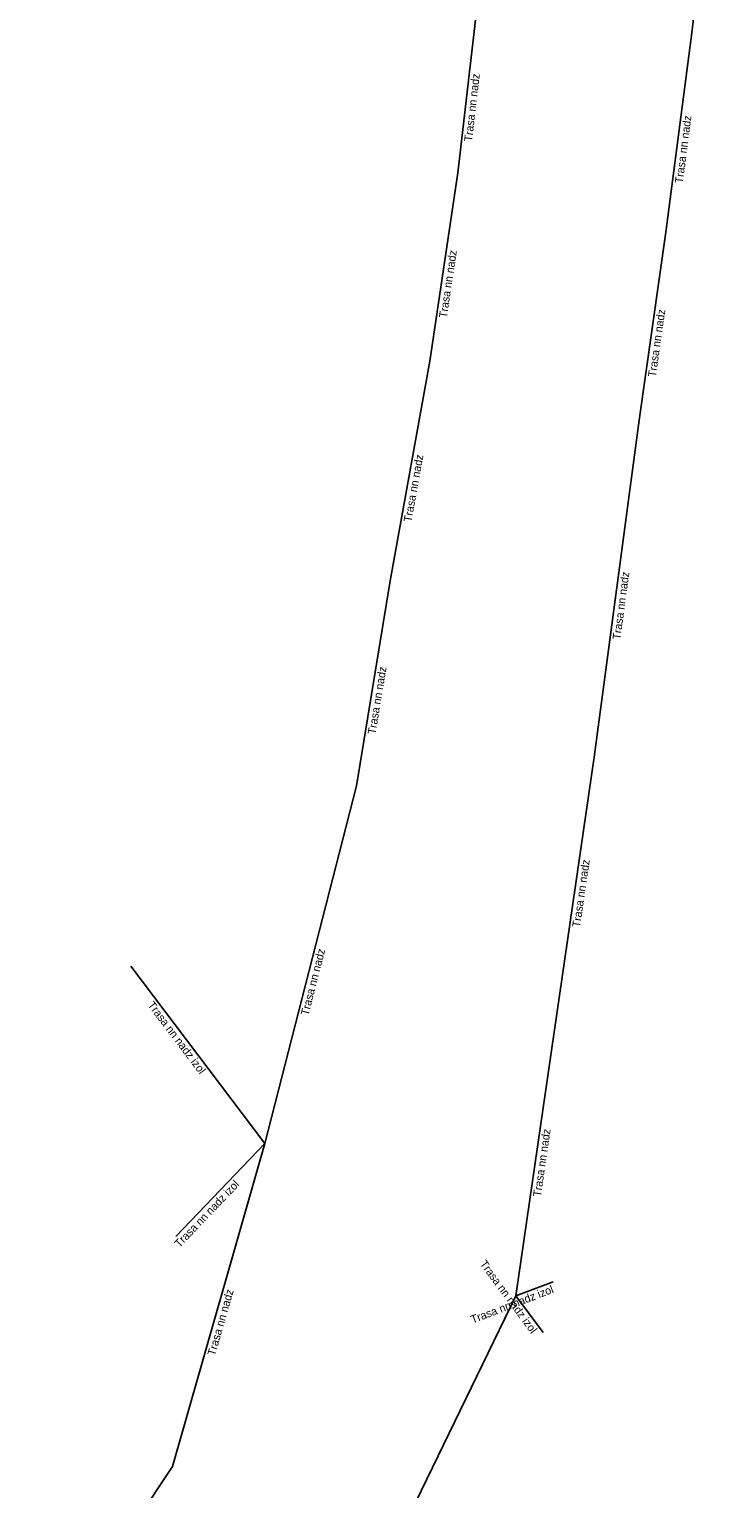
# Model space of a CAD drawing. Extents: x -772942 to -772530, y -1033745 to -1033298.
# Drawn here: x -772845.2 to -772802.4, y -1033493.3 to -1033402.1 of the extents above; entities that cross this region are included whole.
import ezdxf

# ---------------------------------------------------------------- set-up
doc = ezdxf.new("R2010")
doc.units = 0
doc.layers.add('Popiskový text - Ostatní atributy Trasy', color=7, linetype='Continuous')
doc.layers.add('Spojnice NN', color=7, linetype='Continuous')

msp = doc.modelspace()

# ---------------------------------------------------------------- linework, layer by layer
at = {"layer": 'Spojnice NN'}
for points in [[(-772803.783, -1033402.328), (-772802.408, -1033390.528)], [(-772818.393, -1033411.073), (-772817.209, -1033400.814)], [(-772805.397, -1033414.774), (-772803.783, -1033402.328)], [(-772820.15, -1033422.849), (-772818.393, -1033411.073)], [(-772807.07, -1033426.538), (-772805.397, -1033414.774)], [(-772822.626, -1033436.582), (-772820.15, -1033422.849)], [(-772809.879, -1033447.599), (-772807.07, -1033426.538)], [(-772824.733, -1033449.385), (-772822.626, -1033436.582)], [(-772812.043, -1033462.494), (-772809.879, -1033447.599)], [(-772830.454, -1033471.742), (-772824.733, -1033449.385)], [(-772838.843, -1033460.652), (-772830.454, -1033471.742)], [(-772814.771, -1033481.263), (-772812.043, -1033462.494)], [(-772836.223, -1033491.921), (-772830.454, -1033471.742)], [(-772836.015, -1033477.558), (-772830.454, -1033471.742)], [(-772814.771, -1033481.263), (-772812.452, -1033480.375)], [(-772828.67, -1033509.88), (-772814.771, -1033481.263)], [(-772814.771, -1033481.263), (-772813.08, -1033483.556)], [(-772836.223, -1033491.921), (-772845.188, -1033505.391)]]:
    msp.add_lwpolyline(points, dxfattribs=at)

# ---------------------------------------------------------------- texts
at = {"layer": 'Popiskový text - Ostatní atributy Trasy'}
for s, rotation, p in [('Trasa nn nadz', 83.41657, (-772817.517, -1033409.145)), ('Trasa nn nadz', 82.61111, (-772804.35, -1033411.756)), ('Trasa nn nadz', 81.51397, (-772819.093, -1033420.17)), ('Trasa nn nadz', 81.90604, (-772806.033, -1033423.863)), ('Trasa nn nadz', 79.77962, (-772821.306, -1033432.928)), ('Trasa nn nadz', 82.40304, (-772808.246, -1033440.274)), ('Trasa nn nadz', 80.65456, (-772823.549, -1033446.194)), ('Trasa nn nadz', 81.73168, (-772810.77, -1033458.255)), ('Trasa nn nadz', 75.64642, (-772827.744, -1033463.774)), ('Trasa nn nadz izol', 307.10394, (-772837.815, -1033463.088)), ('Trasa nn nadz', 81.7318, (-772813.216, -1033475.087)), ('Trasa nn nadz izol', 46.28774, (-772835.798, -1033478.273)), ('Trasa nn nadz izol', 306.40736, (-772817.054, -1033479.262)), ('Trasa nn nadz', 74.04523, (-772833.579, -1033485.036)), ('Trasa nn nadz izol', 20.95303, (-772817.478, -1033482.996))]:
    msp.add_text(s, height=0.5, rotation=rotation, dxfattribs=at).set_placement(p)

doc.saveas('drawing.dxf')
